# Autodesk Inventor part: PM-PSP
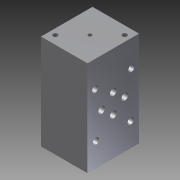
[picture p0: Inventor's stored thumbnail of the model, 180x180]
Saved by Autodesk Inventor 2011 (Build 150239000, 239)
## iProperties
Created: 2010-12
Part Number: PM-PSP
Document SubType Name: Modeling
Designer: sazanov
Density: 1 g/cm^3
Mass: 150.721 g
Surface Area: 267.862 cm^2
Volume: 150.721 cm^3
Author: sazanov
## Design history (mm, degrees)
sketch "Эскиз1"
  geometry: L1 (0, 0)-(0, 46); L2 (0, 46)-(41.5, 46); L3 (41.5, 46)-(41.5, 0); L4 (41.5, 0)-(0, 0)
  constraints: 8 end point, 1 parallel, 1 perpendicular
  dimensions: "d0" = 46 distance of L1.start L1.end; "d1" = 41.5 distance of L1.end L2.end; "d2" = 46 distance of L2.end L3.end
extrude "Выдавливание1" new body sketch "Эскиз1" distance "d3" = 85; taper "d4" = 0 deg
sketch "Эскиз2"
  geometry: 9 further points
  dimensions: "d5" = 21 horizontal distance of point (0, 46) point (21, 38.5); "d6" = 7.5 vertical distance of point (0, 46) point (21, 38.5); "d7" = 0.75 vertical distance of point (61.5, 39.25) point (21, 38.5); "d8" = 40.5 horizontal distance of point (61.5, 39.25) point (21, 38.5); "d9" = 31.75 vertical distance of point (61.5, 6.75) point (21, 38.5); "d10" = 31 distance of point (21, 38.5) point (21, 7.5); "d11" = 40.5 horizontal distance of point (61.5, 6.75) point (21, 7.5); "d12" = 21.5 horizontal distance of point (21, 38.5) point (42.5, 33.4); "d13" = 21.5 horizontal distance of point (21, 38.5) point (42.5, 12.6); "d14" = 5.1 vertical distance of point (21, 38.5) point (42.5, 33.4); "d15" = 15.5 vertical distance of point (51.2, 23) point (21, 38.5); "d16" = 15.5 vertical distance of point (21, 38.5) point (33.7, 23); "d17" = 25.9 vertical distance of point (21, 38.5) point (42.5, 12.6); "d18" = 12.7 horizontal distance of point (21, 38.5) point (33.7, 23); "d19" = 30.2 horizontal distance of point (21, 38.5) point (51.2, 23)
hole "Отверстие1" sketch "Эскиз2" diameter "d20" = 5.5; stored, may be unused: countersink angle "d24" = 90 deg, drill point angle "d26" = 118 deg; dims "d21" = 6, "d22" = 4, "d23" = 2, "d25" = 8
hole "Отверстие2" sketch "Эскиз2" diameter "d27" = 6; stored, may be unused: countersink angle "d31" = 90 deg, drill point angle "d33" = 118 deg; dims "d28" = 6, "d29" = 9, "d30" = 2, "d32" = 8
sketch "Эскиз3"
  geometry: L1 (0, 46)-(-41.5, 46) reference; L2 (-41.5, 46)-(-41.5, 0) reference; L3 (-41.5, 0)-(0, 0) reference; 3 further points
  dimensions: "d34" = 31 horizontal distance of point (-5.25, 7.5) point (-36.25, 38.5); "d35" = 7.5 distance from line of L1 point (-36.25, 38.5); "d36" = 31 horizontal distance of point (-5.25, 7.5) point (-36.25, 38.5); "d37" = 5.25 horizontal distance of L3.end point (-5.25, 7.5); "d38" = 20.75 distance from line of L2 point (-20.75, 23); "d39" = 23 distance from line of L3 point (-20.75, 23)
hole "Отверстие3" sketch "Эскиз3" diameter "d40" = 4.134; stored, may be unused: countersink angle "d44" = 90 deg, drill point angle "d46" = 118 deg; dims "d41" = 6, "d42" = 4, "d43" = 2, "d45" = 8
hole "Отверстие4" sketch "Эскиз3" diameter "d47" = 3.242; stored, may be unused: countersink angle "d51" = 90 deg, drill point angle "d53" = 118 deg; dims "d48" = 6, "d49" = 4, "d50" = 2, "d52" = 8
node "Твердое тело1"
